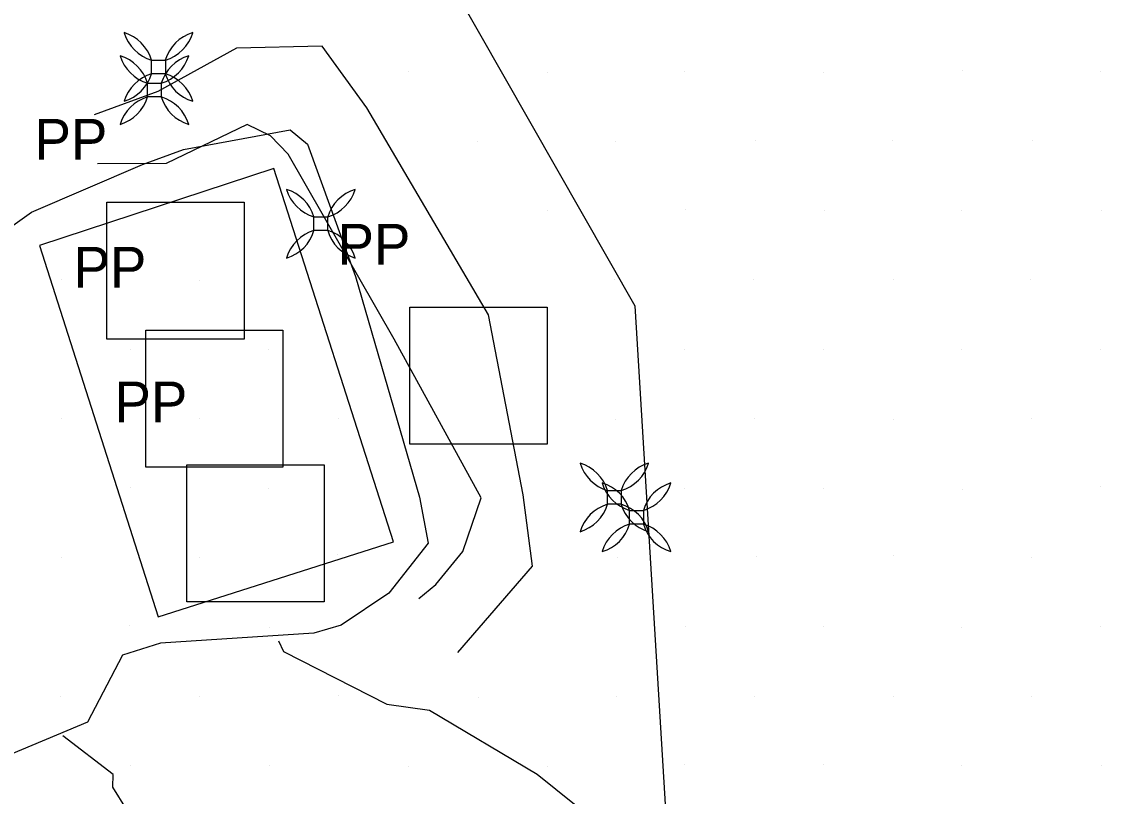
# Model space of a CAD drawing. Extents: x 1602514 to 1609837, y 863887 to 871157.
# Drawn here: x 1605707.9 to 1605875.4, y 865919.5 to 866038 of the extents above; entities that cross this region are included whole.
import ezdxf

# ---------------------------------------------------------------- set-up
doc = ezdxf.new("R2010")
doc.units = 0
for name, color, linetype in [('Photo-Anchor', 7, 'Continuous'), ('Survey-Entrances', 7, 'Continuous'), ('Survey-Fences', 7, 'Continuous'), ('Survey-Ridge Lines', 7, 'Continuous'), ('Survey-Spot dirt', 7, 'Continuous'), ('Survey-Vegetation trees', 7, 'Continuous'), ('Utility-Pole', 7, 'Continuous')]:
    doc.layers.add(name, color=color, linetype=linetype)

msp = doc.modelspace()

# ---------------------------------------------------------------- linework, layer by layer
at = {"layer": 'Photo-Anchor'}
for points in [[(1605727.76, 866032.1), (1605729.86, 866032.1), (1605729.86, 866030), (1605727.76, 866030)], [(1605727.76, 866032.1), (1605729.86, 866032.1), (1605729.86, 866030), (1605727.76, 866030)], [(1605727.13, 866028.57), (1605729.23, 866028.57), (1605729.23, 866026.47), (1605727.13, 866026.47)], [(1605727.13, 866028.57), (1605729.23, 866028.57), (1605729.23, 866026.47), (1605727.13, 866026.47)], [(1605752.61, 866008.12), (1605754.71, 866008.12), (1605754.71, 866006.02), (1605752.61, 866006.02)], [(1605752.61, 866008.12), (1605754.71, 866008.12), (1605754.71, 866006.02), (1605752.61, 866006.02)], [(1605797.55, 865966.23), (1605799.65, 865966.23), (1605799.65, 865964.13), (1605797.55, 865964.13)], [(1605797.55, 865966.23), (1605799.65, 865966.23), (1605799.65, 865964.13), (1605797.55, 865964.13)], [(1605800.94, 865963.19), (1605803.04, 865963.19), (1605803.04, 865961.09), (1605800.94, 865961.09)], [(1605800.94, 865963.19), (1605803.04, 865963.19), (1605803.04, 865961.09), (1605800.94, 865961.09)]]:
    msp.add_lwpolyline(points, close=True, dxfattribs=at)
for centre, radius, start, end in [((1605721.75, 866030.3), 6.27, 16.7236, 73.2821), ((1605729.58, 866038.12), 6.29, 196.8106, 253.1951), ((1605721.75, 866030.3), 6.27, 16.7236, 73.2821), ((1605729.58, 866038.12), 6.29, 196.8106, 253.1951), ((1605735.86, 866030.3), 6.27, 106.7179, 163.2764), ((1605728.04, 866038.12), 6.29, 286.8049, 343.1894), ((1605735.86, 866030.3), 6.27, 106.7179, 163.2764), ((1605728.04, 866038.12), 6.29, 286.8049, 343.1894), ((1605721.13, 866026.76), 6.27, 16.7236, 73.2821), ((1605728.95, 866034.58), 6.29, 196.8106, 253.1951), ((1605721.13, 866026.76), 6.27, 16.7236, 73.2821), ((1605728.95, 866034.58), 6.29, 196.8106, 253.1951), ((1605735.24, 866026.76), 6.27, 106.7179, 163.2764), ((1605727.41, 866034.58), 6.29, 286.8049, 343.1894), ((1605735.24, 866026.76), 6.27, 106.7179, 163.2764), ((1605727.41, 866034.58), 6.29, 286.8049, 343.1894), ((1605721.75, 866031.81), 6.27, 286.7179, 343.2764), ((1605729.58, 866023.98), 6.29, 106.8049, 163.1894), ((1605721.75, 866031.81), 6.27, 286.7179, 343.2764), ((1605729.58, 866023.98), 6.29, 106.8049, 163.1894), ((1605735.86, 866031.81), 6.27, 196.7236, 253.2821), ((1605728.04, 866023.98), 6.29, 16.8106, 73.1951), ((1605735.86, 866031.81), 6.27, 196.7236, 253.2821), ((1605728.04, 866023.98), 6.29, 16.8106, 73.1951), ((1605721.13, 866028.27), 6.27, 286.7179, 343.2764), ((1605728.95, 866020.45), 6.29, 106.8049, 163.1894), ((1605721.13, 866028.27), 6.27, 286.7179, 343.2764), ((1605728.95, 866020.45), 6.29, 106.8049, 163.1894), ((1605735.24, 866028.27), 6.27, 196.7236, 253.2821), ((1605727.41, 866020.45), 6.29, 16.8106, 73.1951), ((1605735.24, 866028.27), 6.27, 196.7236, 253.2821), ((1605727.41, 866020.45), 6.29, 16.8106, 73.1951), ((1605746.61, 866006.31), 6.27, 16.7236, 73.2821), ((1605754.43, 866014.13), 6.29, 196.8106, 253.1951), ((1605746.61, 866006.31), 6.27, 16.7236, 73.2821), ((1605754.43, 866014.13), 6.29, 196.8106, 253.1951), ((1605760.72, 866006.31), 6.27, 106.7179, 163.2764), ((1605752.9, 866014.13), 6.29, 286.8049, 343.1894), ((1605760.72, 866006.31), 6.27, 106.7179, 163.2764), ((1605752.9, 866014.13), 6.29, 286.8049, 343.1894), ((1605746.61, 866007.82), 6.27, 286.7179, 343.2764), ((1605754.43, 866000), 6.29, 106.8049, 163.1894), ((1605746.61, 866007.82), 6.27, 286.7179, 343.2764), ((1605754.43, 866000), 6.29, 106.8049, 163.1894), ((1605760.72, 866007.82), 6.27, 196.7236, 253.2821), ((1605752.9, 866000), 6.29, 16.8106, 73.1951), ((1605760.72, 866007.82), 6.27, 196.7236, 253.2821), ((1605752.9, 866000), 6.29, 16.8106, 73.1951), ((1605791.54, 865964.43), 6.27, 16.7236, 73.2821), ((1605799.37, 865972.25), 6.29, 196.8106, 253.1951), ((1605791.54, 865964.43), 6.27, 16.7236, 73.2821), ((1605799.37, 865972.25), 6.29, 196.8106, 253.1951), ((1605805.65, 865964.43), 6.27, 106.7179, 163.2764), ((1605797.83, 865972.25), 6.29, 286.8049, 343.1894), ((1605805.65, 865964.43), 6.27, 106.7179, 163.2764), ((1605797.83, 865972.25), 6.29, 286.8049, 343.1894), ((1605794.94, 865961.39), 6.27, 16.7236, 73.2821), ((1605802.76, 865969.21), 6.29, 196.8106, 253.1951), ((1605794.94, 865961.39), 6.27, 16.7236, 73.2821), ((1605802.76, 865969.21), 6.29, 196.8106, 253.1951), ((1605809.05, 865961.39), 6.27, 106.7179, 163.2764), ((1605801.23, 865969.21), 6.29, 286.8049, 343.1894), ((1605809.05, 865961.39), 6.27, 106.7179, 163.2764), ((1605801.23, 865969.21), 6.29, 286.8049, 343.1894), ((1605791.54, 865965.93), 6.27, 286.7179, 343.2764), ((1605799.37, 865958.11), 6.29, 106.8049, 163.1894), ((1605791.54, 865965.93), 6.27, 286.7179, 343.2764), ((1605799.37, 865958.11), 6.29, 106.8049, 163.1894), ((1605805.65, 865965.93), 6.27, 196.7236, 253.2821), ((1605797.83, 865958.11), 6.29, 16.8106, 73.1951), ((1605805.65, 865965.93), 6.27, 196.7236, 253.2821), ((1605797.83, 865958.11), 6.29, 16.8106, 73.1951), ((1605794.94, 865962.89), 6.27, 286.7179, 343.2764), ((1605802.76, 865955.07), 6.29, 106.8049, 163.1894), ((1605794.94, 865962.89), 6.27, 286.7179, 343.2764), ((1605802.76, 865955.07), 6.29, 106.8049, 163.1894), ((1605809.05, 865962.89), 6.27, 196.7236, 253.2821), ((1605801.23, 865955.07), 6.29, 16.8106, 73.1951), ((1605809.05, 865962.89), 6.27, 196.7236, 253.2821), ((1605801.23, 865955.07), 6.29, 16.8106, 73.1951)]:
    msp.add_arc(centre, radius, start, end, dxfattribs=at)
at = {"layer": 'Survey-Entrances'}
for points in [[(1605697.86, 866000.6), (1605709.39, 866008.81), (1605726.37, 866016.13), (1605732.63, 866018.4), (1605748.96, 866021.41), (1605751.64, 866019.22), (1605758.95, 865998.98), (1605768.78, 865965.24), (1605770.08, 865958.17), (1605764.07, 865950.53), (1605756.76, 865945.65), (1605752.61, 865944.43), (1605729.14, 865942.89), (1605723.29, 865941.02), (1605717.92, 865930.78), (1605704.68, 865925.25)], [(1605697.86, 866000.6), (1605709.39, 866008.81), (1605726.37, 866016.13), (1605732.63, 866018.4), (1605748.96, 866021.41), (1605751.64, 866019.22), (1605758.95, 865998.98), (1605768.78, 865965.24), (1605770.08, 865958.17), (1605764.07, 865950.53), (1605756.76, 865945.65), (1605752.61, 865944.43), (1605729.14, 865942.89), (1605723.29, 865941.02), (1605717.92, 865930.78), (1605704.68, 865925.25)], [(1605747.2, 865943.21), (1605747.94, 865941.58), (1605763.78, 865933.54), (1605770.28, 865932.64), (1605786.77, 865922.81), (1605801.07, 865911.35)], [(1605747.2, 865943.21), (1605747.94, 865941.58), (1605763.78, 865933.54), (1605770.28, 865932.64), (1605786.77, 865922.81), (1605801.07, 865911.35)], [(1605723.93, 865917.48), (1605721.81, 865920.82), (1605721.89, 865922.77), (1605714.18, 865928.7)], [(1605723.93, 865917.48), (1605721.81, 865920.82), (1605721.89, 865922.77), (1605714.18, 865928.7)]]:
    msp.add_lwpolyline(points, dxfattribs=at)
at = {"layer": 'Survey-Fences'}
msp.add_lwpolyline([(1605728.74, 865946.92), (1605764.79, 865958.41), (1605746.48, 866015.53), (1605710.59, 866003.72), (1605728.74, 865946.92)], dxfattribs=at)
msp.add_lwpolyline([(1605728.74, 865946.92), (1605764.79, 865958.41), (1605746.48, 866015.53), (1605710.59, 866003.72), (1605728.74, 865946.92)], dxfattribs=at)
at = {"layer": 'Survey-Ridge Lines'}
for points in [[(1605774.62, 865941.46), (1605786.06, 865954.67), (1605784.62, 865965.59), (1605779.31, 865993.13), (1605760.73, 866024.81), (1605753.89, 866034.23), (1605740.74, 866033.94), (1605728.72, 866027.32), (1605718.96, 866023.72)], [(1605774.62, 865941.46), (1605786.06, 865954.67), (1605784.62, 865965.59), (1605779.31, 865993.13), (1605760.73, 866024.81), (1605753.89, 866034.23), (1605740.74, 866033.94), (1605728.72, 866027.32), (1605718.96, 866023.72)], [(1605768.69, 865949.7), (1605771.27, 865951.88), (1605775.42, 865956.91), (1605778.22, 865965.12), (1605764.87, 865989.38), (1605748.67, 866017.7), (1605745.98, 866020.53), (1605742.37, 866022.27), (1605729.98, 866016.27), (1605719.46, 866016.21)], [(1605768.69, 865949.7), (1605771.27, 865951.88), (1605775.42, 865956.91), (1605778.22, 865965.12), (1605764.87, 865989.38), (1605748.67, 866017.7), (1605745.98, 866020.53), (1605742.37, 866022.27), (1605729.98, 866016.27), (1605719.46, 866016.21)]]:
    msp.add_lwpolyline(points, dxfattribs=at)
at = {"layer": 'Survey-Spot dirt'}
for p, q in [((1605767.03, 866030.43), (1605767.03, 866030.43)), ((1605767.03, 866030.43), (1605767.03, 866030.43)), ((1605788.36, 866030.21), (1605788.36, 866030.21)), ((1605788.36, 866030.21), (1605788.36, 866030.21)), ((1605809.31, 866030.43), (1605809.31, 866030.43)), ((1605809.31, 866030.43), (1605809.31, 866030.43)), ((1605830.65, 866030.15), (1605830.65, 866030.15)), ((1605830.65, 866030.15), (1605830.65, 866030.15)), ((1605851.83, 866030.47), (1605851.83, 866030.47)), ((1605851.83, 866030.47), (1605851.83, 866030.47)), ((1605873.08, 866030.29), (1605873.08, 866030.29)), ((1605873.08, 866030.29), (1605873.08, 866030.29)), ((1605777.72, 866019.61), (1605777.72, 866019.61)), ((1605777.72, 866019.61), (1605777.72, 866019.61)), ((1605798.81, 866019.64), (1605798.81, 866019.64)), ((1605798.81, 866019.64), (1605798.81, 866019.64)), ((1605820.17, 866019.8), (1605820.17, 866019.8)), ((1605820.17, 866019.8), (1605820.17, 866019.8)), ((1605841.21, 866019.78), (1605841.21, 866019.78)), ((1605841.21, 866019.78), (1605841.21, 866019.78)), ((1605862.55, 866019.78), (1605862.55, 866019.78)), ((1605862.55, 866019.78), (1605862.55, 866019.78)), ((1605724.46, 866009.07), (1605724.46, 866009.07)), ((1605724.46, 866009.07), (1605724.46, 866009.07)), ((1605788.31, 866009.15), (1605788.31, 866009.15)), ((1605788.31, 866009.15), (1605788.31, 866009.15)), ((1605809.47, 866009.19), (1605809.47, 866009.19)), ((1605809.47, 866009.19), (1605809.47, 866009.19)), ((1605830.7, 866009.02), (1605830.7, 866009.02)), ((1605830.7, 866009.02), (1605830.7, 866009.02)), ((1605851.75, 866009.13), (1605851.75, 866009.13)), ((1605851.75, 866009.13), (1605851.75, 866009.13)), ((1605873.15, 866009.07), (1605873.15, 866009.07)), ((1605873.15, 866009.07), (1605873.15, 866009.07)), ((1605713.93, 865998.51), (1605713.93, 865998.51)), ((1605713.93, 865998.51), (1605713.93, 865998.51)), ((1605735.1, 865998.44), (1605735.1, 865998.44)), ((1605735.1, 865998.44), (1605735.1, 865998.44)), ((1605798.62, 865998.58), (1605798.62, 865998.58)), ((1605798.62, 865998.58), (1605798.62, 865998.58)), ((1605819.91, 865998.48), (1605819.91, 865998.48)), ((1605819.91, 865998.48), (1605819.91, 865998.48)), ((1605841.28, 865998.55), (1605841.28, 865998.55)), ((1605841.28, 865998.55), (1605841.28, 865998.55)), ((1605862.38, 865998.58), (1605862.38, 865998.58)), ((1605862.38, 865998.58), (1605862.38, 865998.58)), ((1605724.5, 865987.76), (1605724.5, 865987.76)), ((1605724.5, 865987.76), (1605724.5, 865987.76)), ((1605745.66, 865987.81), (1605745.66, 865987.81)), ((1605745.66, 865987.81), (1605745.66, 865987.81)), ((1605809.38, 865987.77), (1605809.38, 865987.77)), ((1605809.38, 865987.77), (1605809.38, 865987.77)), ((1605830.63, 865987.8), (1605830.63, 865987.8)), ((1605830.63, 865987.8), (1605830.63, 865987.8)), ((1605851.74, 865987.81), (1605851.74, 865987.81)), ((1605851.74, 865987.81), (1605851.74, 865987.81)), ((1605873.1, 865987.82), (1605873.1, 865987.82)), ((1605873.1, 865987.82), (1605873.1, 865987.82)), ((1605713.96, 865977.28), (1605713.96, 865977.28)), ((1605713.96, 865977.28), (1605713.96, 865977.28)), ((1605735.14, 865977.26), (1605735.14, 865977.26)), ((1605735.14, 865977.26), (1605735.14, 865977.26)), ((1605756.34, 865977.19), (1605756.34, 865977.19)), ((1605756.34, 865977.19), (1605756.34, 865977.19)), ((1605798.82, 865977.17), (1605798.82, 865977.17)), ((1605798.82, 865977.17), (1605798.82, 865977.17)), ((1605820.04, 865977.31), (1605820.04, 865977.31)), ((1605820.04, 865977.31), (1605820.04, 865977.31)), ((1605841.34, 865977.09), (1605841.34, 865977.09)), ((1605841.34, 865977.09), (1605841.34, 865977.09)), ((1605862.45, 865977.28), (1605862.45, 865977.28)), ((1605862.45, 865977.28), (1605862.45, 865977.28)), ((1605724.54, 865966.7), (1605724.54, 865966.7)), ((1605724.54, 865966.7), (1605724.54, 865966.7)), ((1605745.72, 865966.6), (1605745.72, 865966.6)), ((1605745.72, 865966.6), (1605745.72, 865966.6)), ((1605809.34, 865966.58), (1605809.34, 865966.58)), ((1605809.34, 865966.58), (1605809.34, 865966.58)), ((1605830.68, 865966.61), (1605830.68, 865966.61)), ((1605830.68, 865966.61), (1605830.68, 865966.61)), ((1605851.92, 865966.45), (1605851.92, 865966.45)), ((1605851.92, 865966.45), (1605851.92, 865966.45)), ((1605873.03, 865966.82), (1605873.03, 865966.82)), ((1605873.03, 865966.82), (1605873.03, 865966.82)), ((1605713.99, 865956.02), (1605713.99, 865956.02)), ((1605713.99, 865956.02), (1605713.99, 865956.02)), ((1605735.09, 865956.02), (1605735.09, 865956.02)), ((1605735.09, 865956.02), (1605735.09, 865956.02)), ((1605756.28, 865956.38), (1605756.28, 865956.38)), ((1605756.28, 865956.38), (1605756.28, 865956.38)), ((1605799.03, 865955.98), (1605799.03, 865955.98)), ((1605799.03, 865955.98), (1605799.03, 865955.98)), ((1605820.37, 865956.13), (1605820.37, 865956.13)), ((1605820.37, 865956.13), (1605820.37, 865956.13)), ((1605841.41, 865956.29), (1605841.41, 865956.29)), ((1605841.41, 865956.29), (1605841.41, 865956.29)), ((1605862.4, 865955.99), (1605862.4, 865955.99)), ((1605862.4, 865955.99), (1605862.4, 865955.99)), ((1605724.42, 865945.51), (1605724.42, 865945.51)), ((1605724.42, 865945.51), (1605724.42, 865945.51)), ((1605745.73, 865945.32), (1605745.73, 865945.32)), ((1605745.73, 865945.32), (1605745.73, 865945.32)), ((1605809.43, 865945.41), (1605809.43, 865945.41)), ((1605809.43, 865945.41), (1605809.43, 865945.41)), ((1605830.63, 865945.4), (1605830.63, 865945.4)), ((1605830.63, 865945.4), (1605830.63, 865945.4)), ((1605851.79, 865945.34), (1605851.79, 865945.34)), ((1605851.79, 865945.34), (1605851.79, 865945.34)), ((1605873.04, 865945.43), (1605873.04, 865945.43)), ((1605873.04, 865945.43), (1605873.04, 865945.43)), ((1605713.86, 865934.79), (1605713.86, 865934.79)), ((1605713.86, 865934.79), (1605713.86, 865934.79)), ((1605735.09, 865934.7), (1605735.09, 865934.7)), ((1605735.09, 865934.7), (1605735.09, 865934.7)), ((1605756.3, 865934.82), (1605756.3, 865934.82)), ((1605756.3, 865934.82), (1605756.3, 865934.82)), ((1605777.77, 865934.6), (1605777.77, 865934.6)), ((1605777.77, 865934.6), (1605777.77, 865934.6)), ((1605798.89, 865934.74), (1605798.89, 865934.74)), ((1605798.89, 865934.74), (1605798.89, 865934.74)), ((1605820.02, 865934.72), (1605820.02, 865934.72)), ((1605820.02, 865934.72), (1605820.02, 865934.72)), ((1605841.31, 865934.74), (1605841.31, 865934.74)), ((1605841.31, 865934.74), (1605841.31, 865934.74)), ((1605862.5, 865934.71), (1605862.5, 865934.71)), ((1605862.5, 865934.71), (1605862.5, 865934.71)), ((1605724.51, 865924.23), (1605724.51, 865924.23)), ((1605724.51, 865924.23), (1605724.51, 865924.23)), ((1605745.78, 865924.22), (1605745.78, 865924.22)), ((1605745.78, 865924.22), (1605745.78, 865924.22)), ((1605767.12, 865924.03), (1605767.12, 865924.03)), ((1605767.12, 865924.03), (1605767.12, 865924.03)), ((1605788.37, 865923.95), (1605788.37, 865923.95)), ((1605788.37, 865923.95), (1605788.37, 865923.95)), ((1605809.4, 865924.38), (1605809.4, 865924.38)), ((1605809.4, 865924.38), (1605809.4, 865924.38)), ((1605830.55, 865924.26), (1605830.55, 865924.26)), ((1605830.55, 865924.26), (1605830.55, 865924.26)), ((1605851.76, 865924.22), (1605851.76, 865924.22)), ((1605851.76, 865924.22), (1605851.76, 865924.22)), ((1605873.14, 865924.11), (1605873.14, 865924.11)), ((1605873.14, 865924.11), (1605873.14, 865924.11))]:
    msp.add_line(p, q, dxfattribs=at)
at = {"layer": 'Survey-Vegetation trees'}
msp.add_lwpolyline([(1605665.45, 866233.32), (1605801.74, 865994.52), (1605807.84, 865893.89), (1606209.37, 865537.1), (1606668.8, 865151.33), (1606667.28, 865042.31)], dxfattribs=at)
msp.add_lwpolyline([(1605665.45, 866233.32), (1605801.74, 865994.52), (1605807.84, 865893.89), (1606209.37, 865537.1), (1606668.8, 865151.33), (1606667.28, 865042.31)], dxfattribs=at)
at = {"layer": 'Utility-Pole'}
for points in [[(1605720.9, 866010.38), (1605741.91, 866010.38), (1605741.91, 865989.38), (1605720.9, 865989.38)], [(1605720.9, 866010.38), (1605741.91, 866010.38), (1605741.91, 865989.38), (1605720.9, 865989.38)], [(1605767.29, 865994.32), (1605788.3, 865994.32), (1605788.3, 865973.31), (1605767.29, 865973.31)], [(1605767.29, 865994.32), (1605788.3, 865994.32), (1605788.3, 865973.31), (1605767.29, 865973.31)], [(1605726.87, 865990.8), (1605747.87, 865990.8), (1605747.87, 865969.79), (1605726.87, 865969.79)], [(1605726.87, 865990.8), (1605747.87, 865990.8), (1605747.87, 865969.79), (1605726.87, 865969.79)], [(1605733.14, 865970.18), (1605754.15, 865970.18), (1605754.15, 865949.18), (1605733.14, 865949.18)], [(1605733.14, 865970.18), (1605754.15, 865970.18), (1605754.15, 865949.18), (1605733.14, 865949.18)]]:
    msp.add_lwpolyline(points, close=True, dxfattribs=at)

# ---------------------------------------------------------------- texts
for p in [(1605709.84, 866016.85), (1605709.84, 866016.85), (1605756.23, 866000.79), (1605756.23, 866000.79), (1605715.81, 865997.27), (1605715.81, 865997.27), (1605722.08, 865976.65), (1605722.08, 865976.65)]:
    msp.add_text('PP', height=6.251, dxfattribs=at).set_placement(p)

doc.saveas('drawing.dxf')
